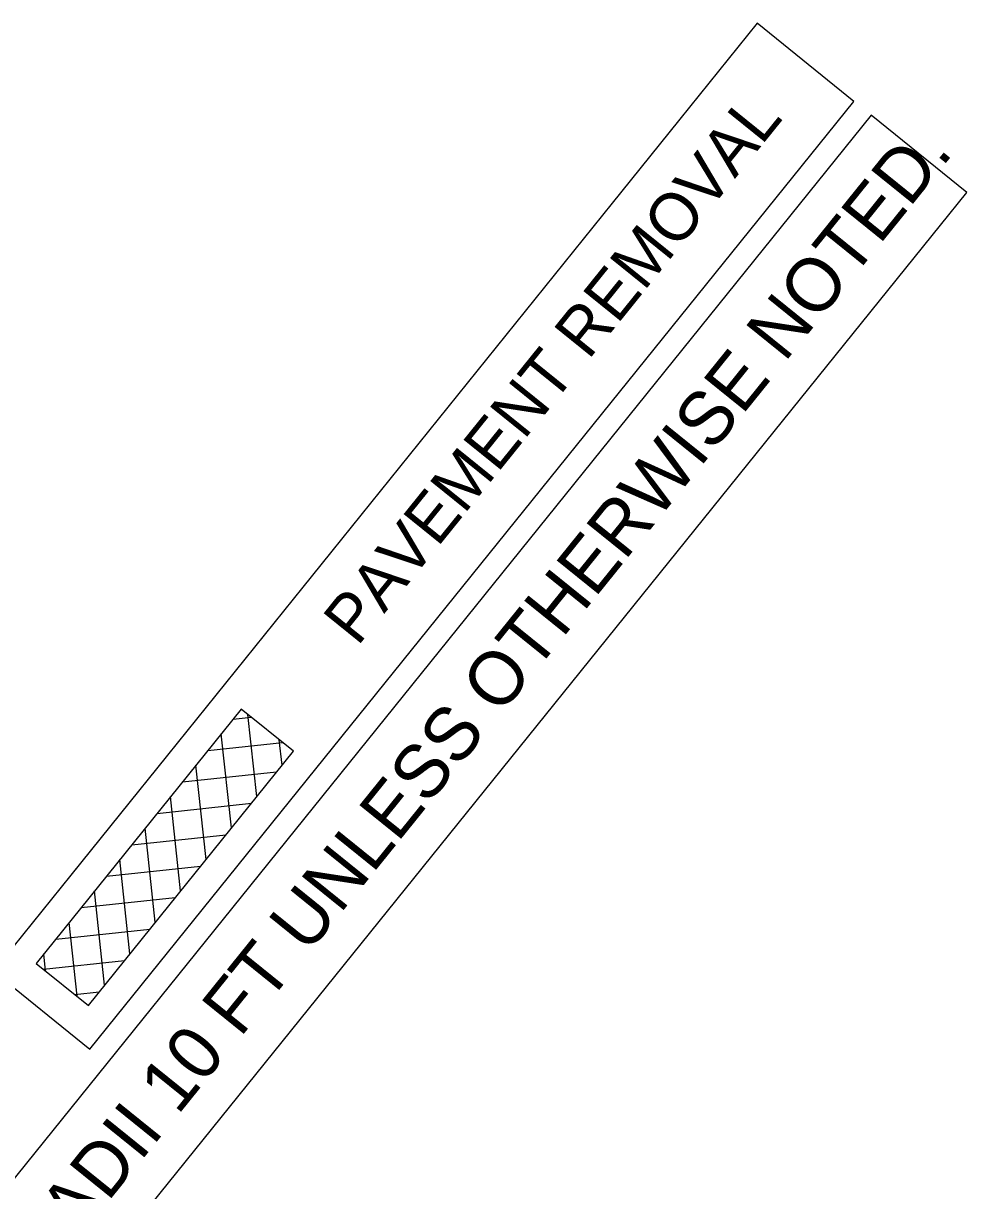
# Model space of a CAD drawing. Extents: x 1487875 to 1489967, y 498345 to 500495.
# Drawn here: x 1489508.5 to 1489607.6, y 500014.7 to 500137.4 of the extents above; entities that cross this region are included whole.
import ezdxf

# ---------------------------------------------------------------- set-up
doc = ezdxf.new("R2010")
doc.units = 0
for name, color, linetype in [('Exist Utilities Gas UG Line SUE LOS B', 7, 'Continuous'), ('Exist Utilities Telephone UG FO SUE LOS B', 7, 'Continuous'), ('Exist Utilities TV Pedestal CELL', 7, 'Continuous'), ('Exist Utilities Water Meter CELL', 7, 'Continuous')]:
    doc.layers.add(name, color=color, linetype=linetype)

msp = doc.modelspace()

# ---------------------------------------------------------------- linework, layer by layer
at = {"layer": 'Exist Utilities TV Pedestal CELL'}
for p, q in [((1489532.99, 500056.14), (1489532.06, 500064.77)), ((1489530.51, 500064.28), (1489532.41, 500064.49)), ((1489530.32, 500052.84), (1489529.26, 500062.73)), ((1489527.85, 500060.98), (1489535.71, 500061.82)), ((1489535.65, 500059.44), (1489535.36, 500062.1)), ((1489525.18, 500057.68), (1489535.08, 500058.74)), ((1489527.66, 500049.53), (1489526.6, 500059.43)), ((1489524.99, 500046.23), (1489523.93, 500056.13)), ((1489522.52, 500054.37), (1489532.42, 500055.43)), ((1489522.33, 500042.93), (1489521.27, 500052.82)), ((1489519.86, 500051.07), (1489529.75, 500052.13)), ((1489517.19, 500047.77), (1489527.09, 500048.83)), ((1489519.67, 500039.62), (1489518.61, 500049.52)), ((1489517, 500036.32), (1489515.94, 500046.22)), ((1489514.53, 500044.47), (1489524.43, 500045.53)), ((1489514.11, 500035.16), (1489513.28, 500042.92)), ((1489511.87, 500041.16), (1489521.76, 500042.22)), ((1489510.58, 500038.01), (1489519.1, 500038.92)), ((1489510.81, 500037.82), (1489510.62, 500039.61)), ((1489513.88, 500035.34), (1489516.44, 500035.62))]:
    msp.add_line(p, q, dxfattribs=at)
at = {"layer": 'Exist Utilities Water Meter CELL'}
for points in [[(1489515.45, 500029.59), (1489595.74, 500129.15), (1489585.57, 500137.36), (1489505.28, 500037.8)], [(1489457.28, 499933.23), (1489607.58, 500119.6), (1489597.54, 500127.7), (1489447.24, 499941.32)], [(1489531.36, 500065.33), (1489509.82, 500038.62), (1489515.3, 500034.2), (1489536.84, 500060.91)]]:
    msp.add_lwpolyline(points, close=True, dxfattribs=at)

# ---------------------------------------------------------------- texts
at = {"layer": 'Exist Utilities Gas UG Line SUE LOS B'}
msp.add_text('NOTE:  ALL DRIVEWAY RADII 10 FT UNLESS OTHERWISE NOTED.', height=5.625, rotation=51.1156, dxfattribs=at).set_placement((1489457.51, 499939.3))
at = {"layer": 'Exist Utilities Telephone UG FO SUE LOS B'}
msp.add_text('PAVEMENT REMOVAL', height=5, rotation=51.1157, dxfattribs=at).set_placement((1489543.57, 500071.83))

doc.saveas('drawing.dxf')
